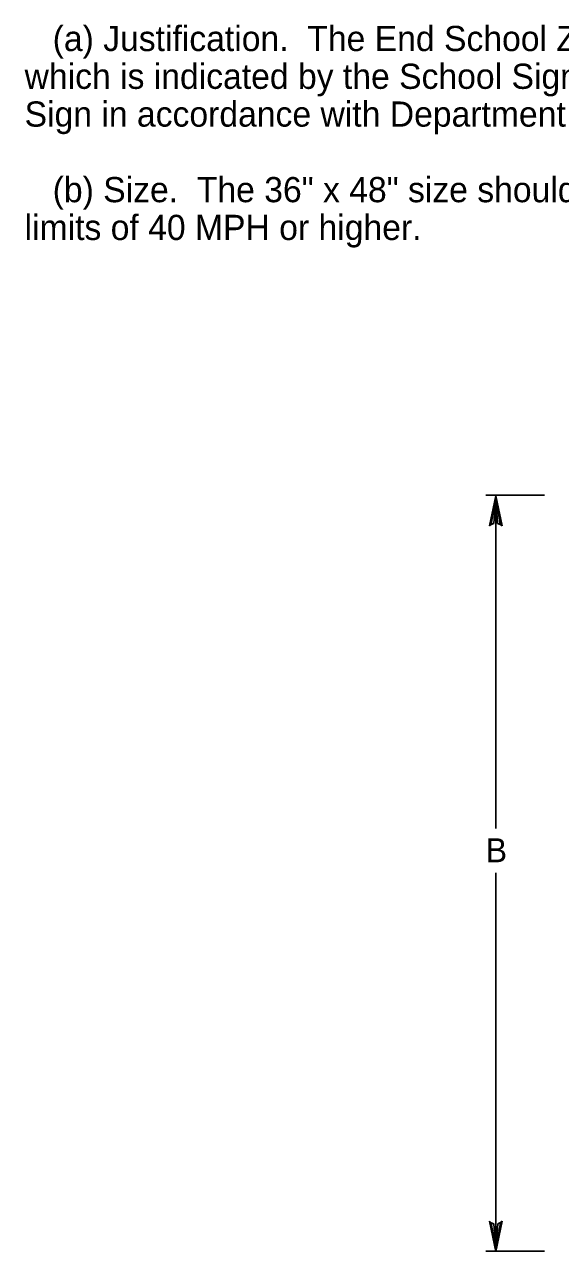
# Model space of a CAD drawing. Extents: x 0.012 to 0.188, y 0.004 to 0.259.
# Drawn here: x 0.0285 to 0.0817, y 0.1174 to 0.2391 of the extents above; entities that cross this region are included whole.
import ezdxf

# ---------------------------------------------------------------- set-up
doc = ezdxf.new("R2010")
doc.units = 0
doc.layers.add('2', color=7, linetype='Continuous')
doc.layers.add('3', color=7, linetype='Continuous')

# ---------------------------------------------------------------- blocks, each defined once
blk = doc.blocks.new('RARROW')
at = {"layer": '3'}
for p, q in [((-2.156, 0.285), (-2.2665, 0.384625)), ((-2.2665, 0.384625), (0, 0)), ((0, 0), (-2.2665, -0.379125)), ((-2.156, 0.285), (-2.075625, 0.12075)), ((0, 0), (-2.156, 0.285)), ((-2.14975, -0.2705), (0, 0)), ((-2.075625, 0.12075), (0, 0)), ((0, 0), (-2.074, -0.108)), ((-2.2665, -0.379125), (-2.14975, -0.2705)), ((-2.074, -0.108), (-2.14975, -0.2705))]:
    blk.add_line(p, q, dxfattribs=at)

msp = doc.modelspace()

# ---------------------------------------------------------------- linework, layer by layer
at = {"layer": '3'}
for p, q in [((0.08009, 0.19242), (0.07425, 0.19242)), ((0.07525, 0.15936), (0.07525, 0.19242)), ((0.07525, 0.15496), (0.07525, 0.11742)), ((0.08009, 0.11742), (0.07425, 0.11742))]:
    msp.add_line(p, q, dxfattribs=at)

# ---------------------------------------------------------------- block references
at = {"layer": '3', "xscale": 0.0013236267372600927, "yscale": 0.0016366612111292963}
for p, rotation in [((0.07525, 0.19237), 89.99999999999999), ((0.07525, 0.11738), -90.00000000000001)]:
    msp.add_blockref('RARROW', p, dxfattribs=dict(at, rotation=rotation))

# ---------------------------------------------------------------- texts
at = {"layer": '2'}
for s, height, p in [('   (a) Justification.  The End School Zone Sign (S5-2) shall be authorized for use at the end of a school zone ', 0.00249975, (0.0285, 0.2365)), ('which is indicated by the School Sign (S1-1), the School Panel (S4-3P) or the Variable School Speed Limit ', 0.00249975, (0.0285, 0.23275)), ('Sign in accordance with Department regulations.', 0.0024998, (0.0285, 0.229)), ('   (b) Size.  The 36" x 48" size should be used on roadways that have four or more lanes with posted speed ', 0.00249975, (0.0285, 0.2215)), ('limits of 40 MPH or higher.', 0.0024998, (0.0285, 0.21775))]:
    msp.add_text(s, height=height, dxfattribs=at).set_placement(p)
at = {"layer": '3'}
msp.add_text('B', height=0.00238, dxfattribs=at).set_placement((0.07425, 0.156))

doc.saveas('drawing.dxf')
